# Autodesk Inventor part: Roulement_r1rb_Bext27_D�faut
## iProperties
Created: 2011-01
Part Number: Roulement_r1rb_Bext27_D�faut
Document SubType Name: Modeling
Designer: eric
Density: 1 g/cm^3
Mass: 1.39224 g
Surface Area: 16.9695 cm^2
Volume: 1.39224 cm^3
Author: eric
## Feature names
1. Base1
